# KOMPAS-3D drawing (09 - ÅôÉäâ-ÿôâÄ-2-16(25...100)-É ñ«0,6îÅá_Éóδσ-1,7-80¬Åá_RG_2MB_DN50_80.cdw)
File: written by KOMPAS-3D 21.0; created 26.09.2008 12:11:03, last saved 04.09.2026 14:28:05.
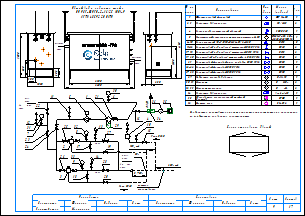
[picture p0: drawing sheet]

Sheets 1-2: A3, landscape

Document properties: Наименование: Макро:21; Автор: RaskoAdmin; Форматы листов документа: 2xA3; Полное имя файла: \\ur38nt01\Departments\КТО\КБ ПУРДГ\Заявки\Прайс-лист на типовые шкафы ГРПШ\ПУРДГ_стандарт_30_04_2026\ПУРДГ с RG_2MB\ПУРДГ-ШУГО-2-16(25...100)-Р до0,6МПа_Рвых-1,7-80кПа_RG_2MB_DN50_80.cdw

Title block, sheet 1: Наименование: Пункт учета газа / ПУГ-Ш-400-Р / ЛГТИ.485922.001ТУ; designation: ЛГТИ.03.4411141; sheet number: 1; Количество листов документа: 2; organisation: ООО "ЭЛЬСТЕР Газэлектроника"; Форматы листов документа: A3; stored path: C:\Рабочие документы\Компас\ПУГ\Схема.cdw; Разработал: Устинов; Проверил: Кошкин; Утвердил: Кошкин
Title block, sheet 2: sheet number: 2; stored path: D:\Рабочие документы\Заявки\ПУРДГ\ПУРДГ-ШУЭО-2-100-Р 4411220.cdw; designation, second copy: ЛГТИ.03.4411141-

Views: Вид 1, Вид 2
Referenced files: wcvoit.frw
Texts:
  Normal
  Общий вид и габариты шкафа
  ПУРДГ-ШУГО-2-16(25...100)-Р
  DN80
  Выход газа
  DN50
  Вход газа
  logo-rasko-ge.png
  DN 1
  местное
  сопротивление
  Римп DN20
  Выход
  газа
  Р=     кПа
  Вход
  Р=       МПа
  PDI
  DN20
  № на
  схеме
  Усл.
  обозн.
  Марка
  (модель)
  Кол.
  Фильтр газовый фланцевый
  ФГ 16-50
  Регулятор давления газа
  RG/2MB
  Клапан предохранительный сбросной
  КПС DN20
  Измерительный комплекс с ротационным счетчиком Ду50
  СГ-ЭК-Р-(0,2...2,0)-
  Кран кнопочный VE-РАСКО-НЗ-1,6-G1/2-М20
  DN15
  Кран шаровой "под приварку" штуцерный DN20 PN16
  Кран шаровой "под приварку" штуцерный DN15 PN16
  Кран шаровой "под приварку" штуцерный п/п DN20 PN16
  Кран шаровой фланцевый с мех. приводом DN50 PN16
  Кран шаровой фланцевый DN50 PN16
  Кран шаровой фланцевый DN80 PN16
  Индикатор перепада давления
  Манометр
  Манометр-напоромер
  Обогреватель газогорелочный шкафной
  (Эльтон")
  Счетчик газа
  Delta 15
  0...     МПа
  0...     кПа
  Venio-A-15
  ОГШН
  BK-G1,6
  Схема открывания дверей
  Предприятие изготовитель может заменять комплектующие на аналогичные,
  не ухудшающие заявленных характеристик.
  Должность
  Конструктор
  Фамилия
  Подпись
  Дата
  Согласовано
  Максимкин
  Лист
  Листов
  POLYLINE_STYLE_0.18_RGB_0_0_0
  POLYLINE_STYLE_0.50_RGB_0_0_0
  POLYLINE_STYLE_0.34_RGB_0_0_0
  PHANTOM_RGB_0_0_0_SC_1_THICK_0.18
  K5LT_THIN_RGB_0_0_0_THICK_0.18
  K5LT32769_RGB_0_0_0_THICK_0.18
  K5LT12_RGB_0_0_0_SC_1_THICK_0.18
  K5LT_DASHED_RGB_0_0_0_SC_1_THICK_0.18
  ACISOTGL_RGB_0_0_0_SC_0.8_THICK_0.25
  CONTINUOUS_RGB_0_127_31_THICK_0.3
  CONTINUOUS_RGB_0_0_255_THICK_0.35
  CONTINUOUS_RGB_255_0_0_THICK_0.35
  POLYLINE_STYLE_0.25_RGB_0_0_0
  CONTINUOUS_RGB_0_0_0_THICK_0.5
  POLYLINE_STYLE_0.35_RGB_0_0_255
  CONTINUOUS_RGB_0_0_0_THICK_0.4
  CONTINUOUS_RGB_0_0_0_THICK_0.35
  НЕВИДИМАЯ_RGB_0_0_0_SC_0.3_THICK_0.25
  СONTINUOUS_RGB_0_0_0_THICK_0.25
  ОСЕВАЯ2_RGB_248_153_30_SC_0.3_THICK_0.25
  Без оформления
Dimensions and other numbers on the sheet: 1; 1500; 250; 300; 1050; 550; 305; 2300; 4130; 2000; 2600; 5,,,7DN 1; 7; 31; 12; 22; 23; 24; 11; 5; 21; 6; 30; 25; 32; 8; 2; 17; 13; 27; 19; 4; 10; 15; 26; 33; 9; 3; 18; 14; 28; 20; 29; 16; 34; 35; 36; 2, 3; 6-10; 11-16; 17, 18; 19, 20; 22-26; 27, 28; 30, 31; 32, 33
